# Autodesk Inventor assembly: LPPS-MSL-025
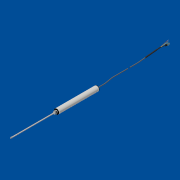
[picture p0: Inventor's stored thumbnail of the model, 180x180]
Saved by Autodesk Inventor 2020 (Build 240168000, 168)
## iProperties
Created: 2019-07
Part Number: LPPS-MSL-025
Document SubType Name: Assembly
Designer: J. Nielson
Author: J. Nielson
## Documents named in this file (5)
- D:\Users\Justin\Documents\CAD Drawings\The Sensor Connection\LPPS\LPPS-MSL\3D\LPPS-MSL-100\LPPS-MSL-100.iam
- D:\Users\Justin\Documents\CAD Drawings\The Sensor Connection\LPPS\LPPS-MSL\3D\MSL PARTS\ISO 4035 - M8BS EN.ipt
- D:\Users\Justin\Documents\CAD Drawings\The Sensor Connection\LPPS\LPPS-MSL\3D\LPPS-MSL-100\LPPS-MSL-100 HOUSING_SW.ipt
- D:\Users\Justin\Documents\CAD Drawings\The Sensor Connection\LPPS\LPPS-MSL\3D\LPPS-MSL-100\LPPS-MSL-100 SHAFT_SW.ipt
- D:\Users\Justin\Documents\CAD Drawings\The Sensor Connection\LPPS\LPPS-MSL\3D\LPPS-MSL-100\LPPS-MSL-100 Spring.ipt
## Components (4 placed, 4 different names)
1. LPPS-MSL-100 HOUSING_SW:1 — Mate:1, Stroke, Mate:3, Flush:1
2. LPPS-MSL-100 SHAFT_SW:1 — Mate:1, Stroke, Angle:2
3. ISO 4035 - M8BS EN:1 — Mate:3, Angle:1, Flush:1
4. LPPS-MSL-100 Spring:1 — Flush:2
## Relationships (7: Mate 3, Angle 2, Flush 2)
- Mate:1: LPPS-MSL-100 HOUSING_SW:1 ↔ LPPS-MSL-100 SHAFT_SW:1
- Stroke [Mate]: LPPS-MSL-100 HOUSING_SW:1 ↔ LPPS-MSL-100 SHAFT_SW:1
- Mate:3: LPPS-MSL-100 HOUSING_SW:1 ↔ ISO 4035 - M8BS EN:1
- Angle:1: ISO 4035 - M8BS EN:1
- Flush:1: LPPS-MSL-100 HOUSING_SW:1 ↔ ISO 4035 - M8BS EN:1
- Flush:2: LPPS-MSL-100 Spring:1
- Angle:2: LPPS-MSL-100 SHAFT_SW:1
